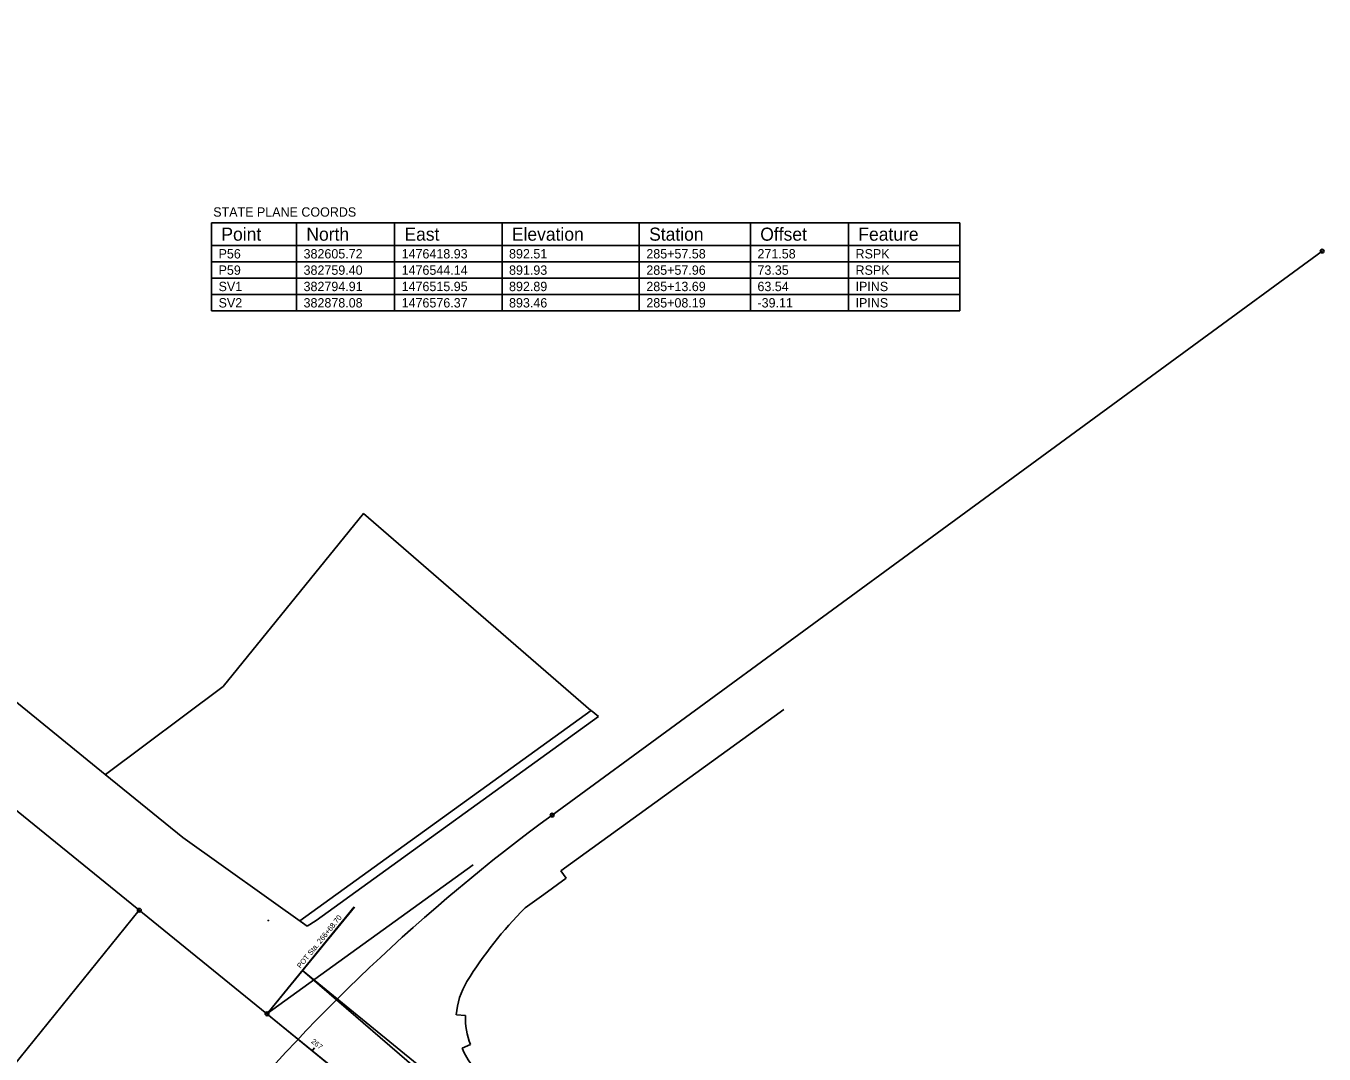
# Model space of a CAD drawing. Extents: x 1474076 to 1484331, y 375914 to 383395.
# Drawn here: x 1476447 to 1477142, y 382807 to 383357 of the extents above; entities that cross this region are included whole.
import ezdxf

# ---------------------------------------------------------------- set-up
doc = ezdxf.new("R2010")
doc.units = 0
for name, color, linetype in [('DV_X_Property_Line', 7, 'Continuous'), ('RW_X_CL_20', 7, 'Continuous'), ('RW_X_Esmt_SH', 7, 'Continuous'), ('RW_X_Fee_RW', 7, 'Continuous'), ('SV_P_Mon_Cells_Set', 7, 'Continuous'), ('SV_X_Mon_Cells_Found', 7, 'Continuous'), ('SV_X_Text', 7, 'Continuous'), ('VG_X_Cells', 7, 'Continuous')]:
    doc.layers.add(name, color=color, linetype=linetype)

msp = doc.modelspace()

# ---------------------------------------------------------------- linework, layer by layer
at = {"layer": 'DV_X_Property_Line'}
msp.add_lwpolyline([(1476489.36, 382956.28), (1476552.48, 383003.4), (1476627.56, 383095.93), (1476749.26, 382990.49)], dxfattribs=at)
at = {"layer": 'RW_X_CL_20'}
for p, q in [((1475924.2, 383357.02), (1476575.86, 382828.12)), ((1476728.51, 382934.52), (1477140.75, 383236.47)), ((1476575.86, 382828.11), (1476686.25, 382907.92)), ((1476576.49, 382828.89), (1476622.61, 382885.38)), ((1476576.49, 382828.89), (1476622.67, 382885.33)), ((1476336.36, 382672.73), (1476507.5, 382883.6)), ((1476575.86, 382828.12), (1477045.83, 382446.68)), ((1476575.86, 382828.12), (1477032.12, 382455.61)), ((1476600.11, 382808.32), (1476601.37, 382809.87))]:
    msp.add_line(p, q, dxfattribs=at)
for centre in [(1477140.75, 383236.47), (1476728.51, 382934.52), (1476507.5, 382883.6), (1476575.86, 382828.12), (1476575.86, 382828.12), (1476575.86, 382828.12)]:
    msp.add_circle(centre, 1, dxfattribs=at)
msp.add_arc((1477319.42, 382127.78), 1000, 126.22135, 140.82833, dxfattribs=at)
at = {"layer": 'RW_X_Esmt_SH'}
for p, q in [((1476594.83, 382851.36), (1477051.09, 382478.84)), ((1476594.86, 382851.34), (1477041.22, 382466.74))]:
    msp.add_line(p, q, dxfattribs=at)
at = {"layer": 'RW_X_Fee_RW'}
for p, q in [((1476387.66, 383038.82), (1476489.27, 382956.35)), ((1476749.44, 382990.62), (1476593.51, 382877.9)), ((1476852.58, 382991.14), (1476733.09, 382904.76)), ((1476753.33, 382987.24), (1476749.44, 382990.62)), ((1476602.18, 382878.08), (1476753.33, 382987.24)), ((1476602.18, 382878.08), (1476753.33, 382987.24)), ((1476489.27, 382956.35), (1476530.81, 382922.63)), ((1476530.81, 382922.63), (1476597.4, 382875.13)), ((1476736.05, 382900.73), (1476724.01, 382892.03)), ((1476733.09, 382904.76), (1476736.05, 382900.73)), ((1476724.01, 382892.03), (1476713.99, 382884.8)), ((1476593.51, 382877.9), (1476597.4, 382875.13)), ((1476597.4, 382875.13), (1476602.18, 382878.08)), ((1476597.4, 382875.13), (1476602.18, 382878.08)), ((1476677.23, 382827.56), (1476682.21, 382827.24)), ((1476684.83, 382811.73), (1476680.28, 382809.72))]:
    msp.add_line(p, q, dxfattribs=at)
for centre, radius, start, end in [((1476865.27, 382733.44), 214, 134.98461, 148.44264), ((1476716.14, 382825.01), 39, 148.42609, 176.25661), ((1476716.14, 382824.99), 34, 176.20988, 202.95817), ((1476716.18, 382824.95), 39, 202.98183, 219.39144)]:
    msp.add_arc(centre, radius, start, end, dxfattribs=at)
at = {"layer": 'SV_P_Mon_Cells_Set'}
for points in [[(1476576.47, 382878.12), (1476576.49, 382878.12)], [(1476576.47, 382878.04), (1476576.49, 382878.04)], [(1476576.48, 382878.04), (1476576.48, 382878.12)], [(1476576.53, 382878.05), (1476576.53, 382878.05), (1476576.53, 382878.05), (1476576.53, 382878.04), (1476576.53, 382878.04), (1476576.53, 382878.04), (1476576.53, 382878.04), (1476576.53, 382878.04), (1476576.52, 382878.04), (1476576.52, 382878.04), (1476576.52, 382878.04), (1476576.52, 382878.05), (1476576.53, 382878.05)], [(1476576.56, 382878.04), (1476576.56, 382878.12), (1476576.58, 382878.12), (1476576.59, 382878.12), (1476576.59, 382878.12), (1476576.59, 382878.11), (1476576.59, 382878.11), (1476576.59, 382878.11), (1476576.6, 382878.11), (1476576.6, 382878.1), (1476576.6, 382878.09), (1476576.6, 382878.09), (1476576.6, 382878.09), (1476576.59, 382878.08), (1476576.59, 382878.08), (1476576.59, 382878.08), (1476576.59, 382878.08), (1476576.58, 382878.08), (1476576.56, 382878.08)], [(1476576.64, 382878.05), (1476576.64, 382878.05), (1476576.64, 382878.05), (1476576.64, 382878.04), (1476576.64, 382878.04), (1476576.64, 382878.04), (1476576.64, 382878.04), (1476576.64, 382878.04), (1476576.64, 382878.04), (1476576.63, 382878.04), (1476576.63, 382878.04), (1476576.64, 382878.05), (1476576.64, 382878.05)], [(1476576.71, 382878.11), (1476576.71, 382878.11), (1476576.7, 382878.11), (1476576.7, 382878.12), (1476576.69, 382878.12), (1476576.69, 382878.12), (1476576.69, 382878.12), (1476576.68, 382878.12), (1476576.67, 382878.11), (1476576.67, 382878.11), (1476576.67, 382878.1), (1476576.67, 382878.1), (1476576.67, 382878.09), (1476576.67, 382878.09), (1476576.7, 382878.07), (1476576.71, 382878.07), (1476576.71, 382878.07), (1476576.71, 382878.06), (1476576.71, 382878.06), (1476576.71, 382878.05), (1476576.71, 382878.05), (1476576.71, 382878.05), (1476576.71, 382878.05), (1476576.7, 382878.04), (1476576.7, 382878.04), (1476576.7, 382878.04), (1476576.7, 382878.04), (1476576.7, 382878.04), (1476576.69, 382878.04), (1476576.68, 382878.04), (1476576.68, 382878.04), (1476576.67, 382878.04), (1476576.67, 382878.05)], [(1476576.75, 382878.05), (1476576.75, 382878.05), (1476576.75, 382878.05), (1476576.75, 382878.04), (1476576.75, 382878.04), (1476576.75, 382878.04), (1476576.75, 382878.04), (1476576.75, 382878.04), (1476576.75, 382878.04), (1476576.74, 382878.04), (1476576.74, 382878.04), (1476576.75, 382878.05), (1476576.75, 382878.05)]]:
    msp.add_lwpolyline(points, dxfattribs=at)
msp.add_circle((1476576.37, 382878.08), 0.06, dxfattribs=at)
at = {"layer": 'SV_X_Mon_Cells_Found'}
msp.add_line((1477140.75, 383236.47), (1477140.75, 383236.47), dxfattribs=at)
msp.add_line((1477140.75, 383236.47), (1477140.75, 383236.47), dxfattribs=at)
for points in [[(1477140.68, 383236.49), (1477140.68, 383236.55), (1477140.73, 383236.55)], [(1477140.68, 383236.49), (1477140.68, 383236.55), (1477140.73, 383236.55)], [(1477140.73, 383236.4), (1477140.68, 383236.4), (1477140.68, 383236.45)], [(1477140.73, 383236.39), (1477140.68, 383236.39), (1477140.68, 383236.45)], [(1477140.71, 383236.42), (1477140.71, 383236.52), (1477140.75, 383236.42), (1477140.79, 383236.52), (1477140.79, 383236.42)], [(1477140.71, 383236.42), (1477140.71, 383236.52), (1477140.75, 383236.42), (1477140.79, 383236.52), (1477140.79, 383236.42)], [(1477140.77, 383236.55), (1477140.83, 383236.55), (1477140.83, 383236.49)], [(1477140.77, 383236.55), (1477140.83, 383236.55), (1477140.83, 383236.49)], [(1477140.83, 383236.45), (1477140.83, 383236.4), (1477140.77, 383236.4)], [(1477140.83, 383236.45), (1477140.83, 383236.39), (1477140.77, 383236.39)]]:
    msp.add_lwpolyline(points, dxfattribs=at)
for centre, radius in [((1476575.86, 382828.12), 0.075), ((1476575.86, 382828.12), 0.075), ((1476575.86, 382828.12), 0.04), ((1476575.86, 382828.12), 0.04), ((1476592.56, 382814.56), 0.075), ((1476592.56, 382814.56), 0.075), ((1476592.56, 382814.56), 0.04), ((1476592.56, 382814.56), 0.04)]:
    msp.add_circle(centre, radius, dxfattribs=at)
at = {"layer": 'VG_X_Cells'}
for p, q in [((1476546.19, 383251.67), (1476946.69, 383251.67)), ((1476546.19, 383251.67), (1476546.19, 383204.42)), ((1476591.69, 383251.67), (1476591.69, 383204.42)), ((1476644.19, 383251.67), (1476644.19, 383204.42)), ((1476701.69, 383251.67), (1476701.69, 383204.42)), ((1476775.19, 383251.67), (1476775.19, 383204.42)), ((1476834.69, 383251.67), (1476834.69, 383204.42)), ((1476887.19, 383251.67), (1476887.19, 383204.42)), ((1476946.69, 383251.67), (1476946.69, 383204.42)), ((1476946.69, 383251.67), (1476946.69, 383204.42)), ((1476546.19, 383239.42), (1476946.69, 383239.42)), ((1476546.19, 383230.67), (1476946.69, 383230.67)), ((1476546.19, 383230.67), (1476946.69, 383230.67)), ((1476546.19, 383230.67), (1476946.69, 383230.67)), ((1476546.19, 383230.67), (1476946.69, 383230.67)), ((1476546.19, 383230.67), (1476946.69, 383230.67)), ((1476546.19, 383230.67), (1476946.69, 383230.67)), ((1476546.19, 383230.67), (1476946.69, 383230.67)), ((1476546.19, 383221.92), (1476946.69, 383221.92)), ((1476546.19, 383221.92), (1476946.69, 383221.92)), ((1476546.19, 383221.92), (1476946.69, 383221.92)), ((1476546.19, 383221.92), (1476946.69, 383221.92)), ((1476546.19, 383221.92), (1476946.69, 383221.92)), ((1476546.19, 383221.92), (1476946.69, 383221.92)), ((1476546.19, 383221.92), (1476946.69, 383221.92)), ((1476546.19, 383213.17), (1476946.69, 383213.17)), ((1476546.19, 383213.17), (1476946.69, 383213.17)), ((1476546.19, 383213.17), (1476946.69, 383213.17)), ((1476546.19, 383213.17), (1476946.69, 383213.17)), ((1476546.19, 383213.17), (1476946.69, 383213.17)), ((1476546.19, 383213.17), (1476946.69, 383213.17)), ((1476546.19, 383213.17), (1476946.69, 383213.17)), ((1476546.19, 383204.42), (1476946.69, 383204.42)), ((1476546.19, 383204.42), (1476946.69, 383204.42)), ((1476546.19, 383204.42), (1476946.69, 383204.42)), ((1476546.19, 383204.42), (1476946.69, 383204.42)), ((1476546.19, 383204.42), (1476946.69, 383204.42)), ((1476546.19, 383204.42), (1476946.69, 383204.42)), ((1476546.19, 383204.42), (1476946.69, 383204.42))]:
    msp.add_line(p, q, dxfattribs=at)

# ---------------------------------------------------------------- texts
at = {"layer": 'RW_X_CL_20'}
for s, rotation, p in [('POT Sta. 266+68.70', 50.76971, (1476593.75, 382852.24)), ('POT Sta. 266+68.70', 50.70966, (1476593.77, 382852.22)), ('267', 320.76971, (1476599.24, 382812.9))]:
    msp.add_text(s, height=2.8, rotation=rotation, dxfattribs=at).set_placement(p)
at = {"layer": 'SV_X_Text'}
msp.add_text('STATE PLANE COORDS', height=5, dxfattribs=at).set_placement((1476547.08, 383254.92))
at = {"layer": 'VG_X_Cells'}
for s, height, p in [('Point', 7, (1476551.44, 383242.05)), ('North', 7, (1476596.94, 383242.05)), ('East', 7, (1476649.44, 383242.05)), ('Elevation', 7, (1476706.94, 383242.05)), ('Station', 7, (1476780.44, 383242.05)), ('Offset', 7, (1476839.94, 383242.05)), ('Feature', 7, (1476892.44, 383242.05)), ('P56', 5, (1476549.94, 383232.55)), ('382605.72', 5, (1476595.44, 383232.55)), ('1476418.93', 5, (1476647.94, 383232.55)), ('892.51', 5, (1476705.44, 383232.55)), ('285+57.58', 5, (1476778.94, 383232.55)), ('271.58', 5, (1476838.44, 383232.55)), ('RSPK', 5, (1476890.94, 383232.55)), ('P59', 5, (1476549.94, 383223.8)), ('382759.40', 5, (1476595.44, 383223.8)), ('1476544.14', 5, (1476647.94, 383223.8)), ('891.93', 5, (1476705.44, 383223.8)), ('285+57.96', 5, (1476778.94, 383223.8)), ('73.35', 5, (1476838.44, 383223.8)), ('RSPK', 5, (1476890.94, 383223.8)), ('SV1', 5, (1476549.94, 383215.05)), ('382794.91', 5, (1476595.44, 383215.05)), ('1476515.95', 5, (1476647.94, 383215.05)), ('892.89', 5, (1476705.44, 383215.05)), ('285+13.69', 5, (1476778.94, 383215.05)), ('63.54', 5, (1476838.44, 383215.05)), ('IPINS', 5, (1476890.94, 383215.05)), ('SV2', 5, (1476549.94, 383206.3)), ('382878.08', 5, (1476595.44, 383206.3)), ('1476576.37', 5, (1476647.94, 383206.3)), ('893.46', 5, (1476705.44, 383206.3)), ('285+08.19', 5, (1476778.94, 383206.3)), ('-39.11', 5, (1476838.44, 383206.3)), ('IPINS', 5, (1476890.94, 383206.3))]:
    msp.add_text(s, height=height, dxfattribs=at).set_placement(p)

doc.saveas('drawing.dxf')
